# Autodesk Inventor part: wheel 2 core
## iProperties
Created: 2010-10
Part Number: wheel 2 core
Document SubType Name: Modeling
Designer: Administrator
Density: 1.4 g/cm^3
Material: PVC-U
Mass: 71.1734 g
Surface Area: 166.499 cm^2
Volume: 50.8382 cm^3
Author: Administrator
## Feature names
1. Base1
